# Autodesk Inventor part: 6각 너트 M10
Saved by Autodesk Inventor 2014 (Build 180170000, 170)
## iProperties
Created: 2026-03
Part Number: 6각 너트 M10
Material: 강철, 연강
Document SubType Name: Modeling
Designer: dg
Density: 7.86 g/cm^3
Appearance: 강철
Mass: 12.2864 g
Surface Area: 10.7153 cm^2
Volume: 1.56316 cm^3
Author: jhkim
Description: 6각 너트 및 6각 가는 너트
Creation Date: 2025-06-27
Sending System: Autodesk Inventor 2026
Preprocessor: ST-DEVELOPER v20.1
Author: dg
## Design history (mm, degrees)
node "6각 너트 M101"
body "Solid1"
node "기준1"
